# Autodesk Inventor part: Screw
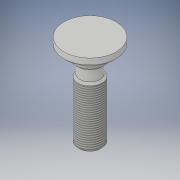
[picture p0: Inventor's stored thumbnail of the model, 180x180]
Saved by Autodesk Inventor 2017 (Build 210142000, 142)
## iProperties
Created: 2017-06
Part Number: Screw
Material: Generic
Document SubType Name: Modeling
Designer: GBR0
Density: 1 g/cm^3
Appearance: Default
Author: GBR0
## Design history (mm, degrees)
sketch "Sketch1"
  geometry: L1 (0, 0)-(0, 30); L2 (0, 0)-(3, 0); L3 (3, 0)-(3, 15); L4 (3, 15)-(2.5, 15); L5 (2.5, 15)-(2.5, 18); L6 (2.5, 18)-(3.5, 18); L7 (3.5, 18)-(3.5, 21); L8 (3.5, 21)-(6.5, 21); L9 (6.5, 21)-(6.5, 23); L10 (6.5, 23)-(0, 23)
  constraints: 20 end point, 6 perpendicular, 3 horizontal, 1 point on line, 1 vertical
  dimensions: "d1" = 3 distance of L1.start L2.end; "d2" = 0.5 distance of L3.end L4.end; "d3" = 3 distance of L4.end L5.end; "d4" = 1 distance of L5.end L6.end; "d5" = 3 distance of L6.end L7.end; "d6" = 3 distance of L7.end L8.end; "d7" = 2 distance of L8.end L9.end; "d8" = 6.5 distance of L9.end L10.end (derived); "d9" = 23 distance between parallel lines of L10 L2; "d10" = 15 distance of L2.end L3.end (derived)
revolve "Revolution1" sketch "Sketch1" stored, may be unused: angle "d11" = 90 deg
chamfer "Chamfer1" distance "d12" = 0.5; stored, may be unused: second distance "d13" = 2, angle "d14" = 45 deg
thread "Thread1" dims "d15" = 10, "d16" = 0
body "Solid1"
